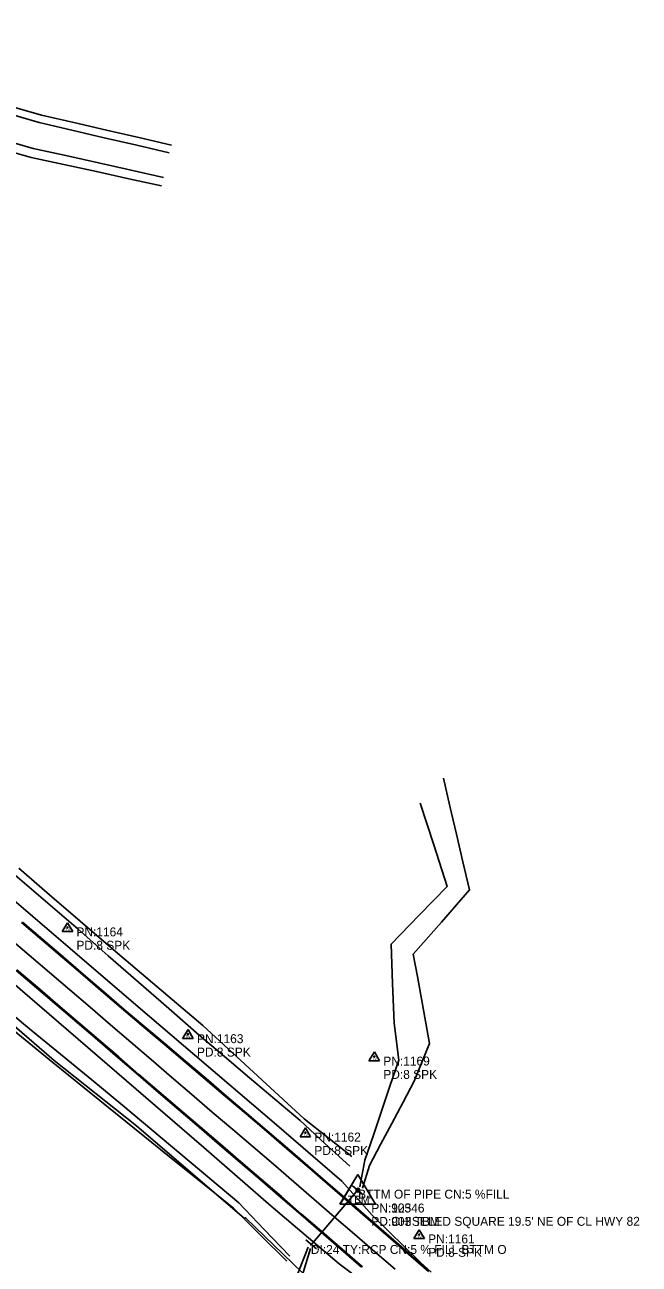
# Model space of a CAD drawing. Extents: x 878399 to 889864, y 1564003 to 1567413.
# Drawn here: x 884094 to 884438, y 1565882 to 1566576 of the extents above; entities that cross this region are included whole.
import ezdxf

# ---------------------------------------------------------------- set-up
doc = ezdxf.new("R2010")
doc.units = 0
for name, color, linetype in [('S_CROSS_DRAIN', 7, 'Continuous'), ('S_CROSS_DRAIN_ANNOT', 7, 'Continuous'), ('S_DITCHLINE', 7, 'Continuous'), ('S_DRG_PT_SYM', 7, 'Continuous'), ('S_EDGE_PAVEMENT', 7, 'Continuous'), ('S_FIBER_OPTIC_CABLE', 7, 'Continuous'), ('S_GRAVEL_ROAD', 7, 'Continuous'), ('S_HEADWALL', 7, 'Continuous'), ('S_PAVEMENT_CROWN', 7, 'Continuous'), ('S_PRIMARY_CTL', 7, 'Continuous'), ('S_PRIMARY_CTL_ANNOT', 7, 'Continuous'), ('S_SECONDARY_CTL', 7, 'Continuous'), ('S_SECONDARY_CTL_ANNOT', 7, 'Continuous'), ('S_SHOULDER', 7, 'Continuous'), ('S_UTL_PT_SYM', 7, 'Continuous')]:
    doc.layers.add(name, color=color, linetype=linetype)

msp = doc.modelspace()

# ---------------------------------------------------------------- linework, layer by layer
at = {"layer": 'S_CROSS_DRAIN'}
msp.add_line((884254.16, 1565892.75), (884280.63, 1565923.74), dxfattribs=at)
at = {"layer": 'S_DITCHLINE'}
for points in [[(884083.22, 1566531.09), (884103.37, 1566525.29), (884121.56, 1566521.09), (884139.76, 1566516.9), (884157.96, 1566512.7), (884176.15, 1566508.5)], [(884076.48, 1566507.61), (884097.56, 1566501.62), (884115.84, 1566497.64), (884134.12, 1566493.65), (884152.4, 1566489.67), (884170.68, 1566485.69)], [(884283.17, 1565924.51), (884286.98, 1565937.21), (884293.25, 1565949.03), (884299.53, 1565960.85), (884305.81, 1565972.67), (884312.09, 1565984.49), (884320.59, 1566005.53), (884318.33, 1566018.02), (884316.06, 1566030.51), (884313.8, 1566043), (884311.53, 1566055.49), (884327.21, 1566073.54), (884342.88, 1566091.6), (884339.27, 1566107.21), (884335.65, 1566122.83), (884332.03, 1566138.44), (884328.42, 1566154.05)], [(884281.56, 1565925.39), (884284.42, 1565940.29), (884289.16, 1565954.25), (884293.9, 1565968.22), (884298.63, 1565982.19), (884303.37, 1565996.15), (884300.84, 1566016.97), (884299.94, 1566039.06), (884299.04, 1566061.15), (884314.76, 1566077.34), (884330.48, 1566093.54), (884322.96, 1566116.85), (884315.44, 1566140.17)], [(884277.04, 1565942.38), (884263.74, 1565952.88), (884250.43, 1565963.38), (884236.25, 1565976.43), (884222.06, 1565989.48), (884207.87, 1566002.53), (884193.69, 1566015.58), (884176.55, 1566030.18), (884159.42, 1566044.78), (884142.29, 1566059.38), (884125.16, 1566073.98), (884107.91, 1566088.85), (884090.66, 1566103.72)], [(884275.91, 1565936.94), (884262.03, 1565949.67), (884248.15, 1565962.39), (884234.03, 1565974.36), (884219.92, 1565986.33), (884205.8, 1565998.3), (884191.69, 1566010.27), (884174.73, 1566025.08), (884157.77, 1566039.89), (884140.81, 1566054.71), (884123.86, 1566069.52), (884105.66, 1566085.17), (884087.47, 1566100.83)], [(884242.45, 1565886.54), (884228.13, 1565901.45), (884213.8, 1565916.37), (884197.57, 1565929.98), (884181.35, 1565943.6), (884165.12, 1565957.21), (884148.89, 1565970.82), (884131.52, 1565985.16), (884114.14, 1565999.51), (884096.77, 1566013.85), (884079.4, 1566028.2), (884062.93, 1566042.65), (884046.46, 1566057.1), (884029.99, 1566071.55), (884013.52, 1566086), (884006.53, 1566091.04)], [(884240.72, 1565883.62), (884225.82, 1565898.5), (884210.91, 1565913.38), (884194.38, 1565926.67), (884177.84, 1565939.96), (884161.31, 1565953.26), (884144.77, 1565966.55), (884127.24, 1565980.78), (884109.7, 1565995.01), (884092.16, 1566009.24), (884074.62, 1566023.47), (884058.32, 1566037.93), (884042.02, 1566052.39), (884025.72, 1566066.85), (884009.41, 1566081.31), (884001.3, 1566085.82)], [(884121.95, 1565693.58), (884112.29, 1565714.29), (884119.13, 1565727.88), (884130.82, 1565741.22), (884142.51, 1565754.56), (884162.92, 1565762.71), (884181.72, 1565777.44), (884200.52, 1565792.16), (884214.44, 1565802.68), (884228.36, 1565813.2), (884233.47, 1565828.33), (884238.58, 1565843.46), (884243.69, 1565858.59), (884248.79, 1565873.71), (884254.05, 1565890.79)], [(884246.5, 1565875.89), (884252.61, 1565891.5)]]:
    msp.add_lwpolyline(points, dxfattribs=at)
at = {"layer": 'S_DRG_PT_SYM'}
for points in [[(884280.63, 1565923.74), (884280.63, 1565923.79), (884280.63, 1565923.74), (884280.58, 1565923.74), (884280.63, 1565923.74), (884280.63, 1565923.69), (884280.63, 1565923.74), (884280.68, 1565923.74)], [(884254.16, 1565892.75), (884254.16, 1565892.8), (884254.16, 1565892.75), (884254.11, 1565892.75), (884254.16, 1565892.75), (884254.16, 1565892.7), (884254.16, 1565892.75), (884254.21, 1565892.75)]]:
    msp.add_lwpolyline(points, dxfattribs=at)
at = {"layer": 'S_EDGE_PAVEMENT'}
for points in [[(884092.29, 1566073.24), (884103.7, 1566063.5), (884115.1, 1566053.75), (884126.49, 1566043.99), (884126.49, 1566043.99), (884126.49, 1566043.99), (884137.92, 1566034.19), (884149.3, 1566024.43), (884160.73, 1566014.71), (884172.19, 1566005.02), (884183.64, 1565995.33), (884195.08, 1565985.63), (884195.08, 1565985.63), (884195.08, 1565985.63), (884206.48, 1565975.89), (884217.89, 1565966.15), (884229.29, 1565956.41), (884240.66, 1565946.62), (884252.03, 1565936.83), (884263.42, 1565927.02), (884263.42, 1565927.02), (884263.42, 1565927.02), (884274.77, 1565917.21), (884286.1, 1565907.38), (884297.42, 1565897.54), (884308.74, 1565887.7), (884320.04, 1565877.9)], [(884092.75, 1566073.49), (884104.15, 1566063.75), (884115.55, 1566054.01), (884126.94, 1566044.24), (884126.94, 1566044.24), (884126.94, 1566044.24), (884138.36, 1566034.44), (884149.75, 1566024.68), (884161.18, 1566014.96), (884172.63, 1566005.28), (884184.08, 1565995.59), (884195.52, 1565985.88), (884195.52, 1565985.88), (884195.52, 1565985.88), (884206.92, 1565976.15), (884218.33, 1565966.4), (884229.74, 1565956.66), (884241.1, 1565946.88), (884252.47, 1565937.09), (884263.86, 1565927.28), (884263.86, 1565927.28), (884263.86, 1565927.28), (884275.21, 1565917.46), (884286.55, 1565907.64), (884297.86, 1565897.8), (884309.18, 1565887.96), (884320.48, 1565878.16)], [(884089.24, 1566046.48), (884100.65, 1566036.75), (884112.07, 1566027.03), (884123.44, 1566017.34), (884134.81, 1566007.54), (884146.17, 1565997.75), (884157.53, 1565987.96), (884168.92, 1565978.19), (884180.31, 1565968.44), (884191.72, 1565958.68), (884203.1, 1565948.91), (884214.47, 1565939.13), (884225.85, 1565929.35), (884237.22, 1565919.56), (884248.53, 1565909.78), (884259.87, 1565899.97), (884271.22, 1565890.15), (884282.58, 1565880.36)], [(884089.69, 1566046.73), (884101.1, 1566037.01), (884112.52, 1566027.28), (884123.89, 1566017.59), (884135.25, 1566007.8), (884146.62, 1565998.01), (884157.98, 1565988.21), (884169.36, 1565978.45), (884180.76, 1565968.69), (884192.16, 1565958.94), (884203.55, 1565949.17), (884214.92, 1565939.39), (884226.29, 1565929.61), (884237.66, 1565919.82), (884248.97, 1565910.04), (884260.32, 1565900.23), (884271.66, 1565890.41), (884283.02, 1565880.62)]]:
    msp.add_lwpolyline(points, dxfattribs=at)
at = {"layer": 'S_FIBER_OPTIC_CABLE'}
for p, q in [((884110.46, 1565996.06), (884058.45, 1566040.97)), ((884156.58, 1565959.49), (884110.46, 1565996.06)), ((884217.07, 1565907.58), (884156.58, 1565959.49)), ((884217.64, 1565908), (884217.07, 1565907.58)), ((884254.77, 1565872.1), (884217.64, 1565908))]:
    msp.add_line(p, q, dxfattribs=at)
at = {"layer": 'S_GRAVEL_ROAD'}
for points in [[(884081.57, 1566527.11), (884102.2, 1566521.06), (884120.38, 1566516.83), (884138.55, 1566512.6), (884156.73, 1566508.38), (884174.9, 1566504.15)], [(884077.97, 1566512.55), (884098.83, 1566506.67), (884117.07, 1566502.58), (884135.31, 1566498.48), (884153.54, 1566494.38), (884171.78, 1566490.28)]]:
    msp.add_lwpolyline(points, dxfattribs=at)
at = {"layer": 'S_HEADWALL'}
for points in [[(884277.44, 1565925.9), (884283.39, 1565920.92)], [(884251.45, 1565895.56), (884257.3, 1565890.59)]]:
    msp.add_lwpolyline(points, dxfattribs=at)
at = {"layer": 'S_PAVEMENT_CROWN'}
msp.add_lwpolyline([(884085.12, 1566064.8), (884096.53, 1566055.06), (884107.94, 1566045.32), (884119.34, 1566035.57), (884130.72, 1566025.81), (884130.72, 1566025.81), (884130.72, 1566025.81), (884142.11, 1566016.05), (884142.11, 1566016.05), (884142.11, 1566016.05), (884153.5, 1566006.28), (884164.88, 1565996.51), (884176.26, 1565986.74), (884176.26, 1565986.74), (884176.26, 1565986.74), (884187.64, 1565976.96), (884199.03, 1565967.21), (884210.43, 1565957.46), (884221.83, 1565947.71), (884233.21, 1565937.93), (884233.21, 1565937.93), (884244.57, 1565928.13), (884244.57, 1565928.13), (884255.93, 1565918.34), (884255.93, 1565918.34), (884255.93, 1565918.34), (884267.29, 1565908.54), (884278.64, 1565898.74), (884290, 1565888.94), (884301.35, 1565879.14)], dxfattribs=at)
at = {"layer": 'S_PRIMARY_CTL'}
for p, q in [((884280.52, 1565932.21), (884270.48, 1565915.7)), ((884280.54, 1565932.15), (884270.51, 1565915.63)), ((884280.52, 1565932.21), (884290.34, 1565915.7)), ((884280.54, 1565932.15), (884290.37, 1565915.63)), ((884270.48, 1565915.7), (884290.34, 1565915.7)), ((884270.51, 1565915.63), (884290.37, 1565915.63))]:
    msp.add_line(p, q, dxfattribs=at)
for centre, radius in [((884280.52, 1565923.51), 1.04), ((884280.54, 1565923.45), 1.04), ((884280.52, 1565923.51), 0.609), ((884280.54, 1565923.45), 0.609), ((884280.52, 1565923.51), 0.344), ((884280.54, 1565923.45), 0.344)]:
    msp.add_circle(centre, radius, dxfattribs=at)
at = {"layer": 'S_SECONDARY_CTL'}
for p, q in [((884117.97, 1566073.15), (884114.96, 1566068.2)), ((884114.96, 1566068.2), (884120.92, 1566068.2)), ((884117.97, 1566073.15), (884120.92, 1566068.2)), ((884185.44, 1566013.37), (884182.43, 1566008.42)), ((884185.44, 1566013.37), (884188.39, 1566008.42)), ((884182.43, 1566008.42), (884188.39, 1566008.42)), ((884289.72, 1566000.84), (884286.71, 1565995.89)), ((884289.72, 1566000.84), (884292.67, 1565995.89)), ((884286.71, 1565995.89), (884292.67, 1565995.89)), ((884251.13, 1565958.28), (884248.12, 1565953.33)), ((884251.13, 1565958.28), (884254.07, 1565953.33)), ((884248.12, 1565953.33), (884254.07, 1565953.33)), ((884314.85, 1565901.27), (884311.84, 1565896.32)), ((884314.85, 1565901.27), (884317.79, 1565896.32)), ((884311.84, 1565896.32), (884317.79, 1565896.32))]:
    msp.add_line(p, q, dxfattribs=at)
for centre, radius in [((884117.97, 1566070.54), 0.311), ((884117.97, 1566070.54), 0.183), ((884117.97, 1566070.54), 0.103), ((884185.44, 1566010.76), 0.311), ((884185.44, 1566010.76), 0.183), ((884185.44, 1566010.76), 0.103), ((884289.72, 1565998.23), 0.311), ((884289.72, 1565998.23), 0.183), ((884289.72, 1565998.23), 0.103), ((884251.13, 1565955.67), 0.311), ((884251.13, 1565955.67), 0.183), ((884251.13, 1565955.67), 0.103), ((884314.85, 1565898.66), 0.311), ((884314.85, 1565898.66), 0.183), ((884314.85, 1565898.66), 0.103)]:
    msp.add_circle(centre, radius, dxfattribs=at)
at = {"layer": 'S_SHOULDER'}
for points in [[(883508.31, 1566575.84), (883547.66, 1566544.44), (883586.44, 1566512.88), (883625.11, 1566480.84), (883663.31, 1566448.58), (883701.62, 1566416.27), (883739.86, 1566383.96), (883777.89, 1566351.48), (883815.94, 1566319.17), (883853.96, 1566286.62), (883891.95, 1566254.11), (883929.94, 1566221.59), (883967.85, 1566188.94), (884005.75, 1566156.31), (884043.67, 1566123.7), (884081.66, 1566091.2), (884119.53, 1566058.67), (884157.51, 1566026.01), (884195.58, 1565993.6), (884233.66, 1565961.2), (884271.59, 1565928.53), (884288.54, 1565909.45), (884315.55, 1565882.9), (884321.54, 1565877.6)], [(883509.1, 1566529.69), (883547.7, 1566498.51), (883586.27, 1566466.69), (883624.58, 1566434.92), (883662.64, 1566402.69), (883700.84, 1566370.42), (883738.86, 1566338.05), (883776.89, 1566305.59), (883814.92, 1566272.98), (883852.88, 1566240.51), (883890.94, 1566208.08), (883928.89, 1566175.58), (883966.88, 1566143.07), (884004.67, 1566110.33), (884042.61, 1566077.76), (884080.7, 1566045.23), (884118.58, 1566012.73), (884156.35, 1565979.97), (884194.27, 1565947.36), (884231.98, 1565914.52), (884270.03, 1565882.19), (884310.06, 1565851.92)]]:
    msp.add_lwpolyline(points, dxfattribs=at)
at = {"layer": 'S_UTL_PT_SYM'}
for points in [[(884110.46, 1565996.06), (884110.46, 1565996.11), (884110.46, 1565996.06), (884110.41, 1565996.06), (884110.46, 1565996.06), (884110.46, 1565996.01), (884110.46, 1565996.06), (884110.51, 1565996.06)], [(884156.58, 1565959.49), (884156.58, 1565959.54), (884156.58, 1565959.49), (884156.53, 1565959.49), (884156.58, 1565959.49), (884156.58, 1565959.44), (884156.58, 1565959.49), (884156.63, 1565959.49)], [(884217.64, 1565908), (884217.64, 1565908.05), (884217.64, 1565908), (884217.59, 1565908), (884217.64, 1565908), (884217.64, 1565907.95), (884217.64, 1565908), (884217.69, 1565908)], [(884217.07, 1565907.58), (884217.07, 1565907.63), (884217.07, 1565907.58), (884217.02, 1565907.58), (884217.07, 1565907.58), (884217.07, 1565907.53), (884217.07, 1565907.58), (884217.12, 1565907.58)]]:
    msp.add_lwpolyline(points, dxfattribs=at)

# ---------------------------------------------------------------- texts
at = {"layer": 'S_CROSS_DRAIN_ANNOT'}
for s, p in [('BTTM OF PIPE CN:5 %FILL', (884280.63, 1565918.74)), ('DI:24 TY:RCP CN:5 % FILL BTTM O', (884254.16, 1565887.75))]:
    msp.add_text(s, height=5, dxfattribs=at).set_placement(p)
at = {"layer": 'S_PRIMARY_CTL'}
for p in [(884274.86, 1565916.12), (884274.89, 1565916.06)]:
    msp.add_text('TBM', height=4.287, rotation=360, dxfattribs=at).set_placement(p)
at = {"layer": 'S_PRIMARY_CTL_ANNOT'}
for s, p in [('PN:903', (884288.02, 1565911.01)), ('PN:12546', (884288.04, 1565910.95)), ("PD:CHISELED SQUARE 19.5' NE OF CL HWY 82", (884288.02, 1565903.51)), ('PD:903 TBM', (884288.04, 1565903.45))]:
    msp.add_text(s, height=5, dxfattribs=at).set_placement(p)
at = {"layer": 'S_SECONDARY_CTL'}
for p in [(884116.77, 1566068.53), (884184.23, 1566008.75), (884288.52, 1565996.22), (884249.92, 1565953.66), (884313.64, 1565896.65)]:
    msp.add_text('TV', height=1.5, rotation=360, dxfattribs=at).set_placement(p)
at = {"layer": 'S_SECONDARY_CTL_ANNOT'}
for s, p in [('PN:1164', (884122.97, 1566065.54)), ('PD:8 SPK', (884122.97, 1566058.04)), ('PN:1163', (884190.44, 1566005.76)), ('PD:8 SPK', (884190.44, 1565998.26)), ('PN:1169', (884294.72, 1565993.23)), ('PD:8 SPK', (884294.72, 1565985.73)), ('PN:1162', (884256.13, 1565950.67)), ('PD:8 SPK', (884256.13, 1565943.17)), ('PN:1161', (884319.85, 1565893.66)), ('PD:8 SPK', (884319.85, 1565886.16))]:
    msp.add_text(s, height=5, dxfattribs=at).set_placement(p)

doc.saveas('drawing.dxf')
